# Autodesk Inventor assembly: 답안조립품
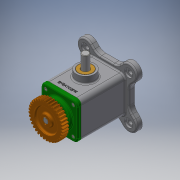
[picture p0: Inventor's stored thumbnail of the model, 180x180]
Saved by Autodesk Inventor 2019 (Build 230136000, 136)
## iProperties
Created: 2021-01
Part Number: 답안조립품
Material: 일반
Document SubType Name: Assembly
Designer: 3dpro9
Author: 3dpro9
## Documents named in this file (11)
- C:\Users\3dpro9\Desktop\710114V1008\답안조립품.iam
- C:\Users\3dpro9\Desktop\710114V1008\본체.ipt
- C:\Users\3dpro9\Desktop\710114V1008\베어링 6203.ipt
- C:\Users\3dpro9\Desktop\710114V1008\볼트 M4.ipt
- C:\Users\3dpro9\Desktop\710114V1008\부시.ipt
- C:\Users\3dpro9\Desktop\710114V1008\스퍼기어.ipt
- C:\Users\3dpro9\Desktop\710114V1008\슬라이더.ipt
- C:\Users\3dpro9\Desktop\710114V1008\오일 실.ipt
- C:\Users\3dpro9\Desktop\710114V1008\커버.ipt
- C:\Users\3dpro9\Desktop\710114V1008\키 4 x 4 x 14.ipt
- C:\Users\3dpro9\Desktop\710114V1008\편심축.ipt
